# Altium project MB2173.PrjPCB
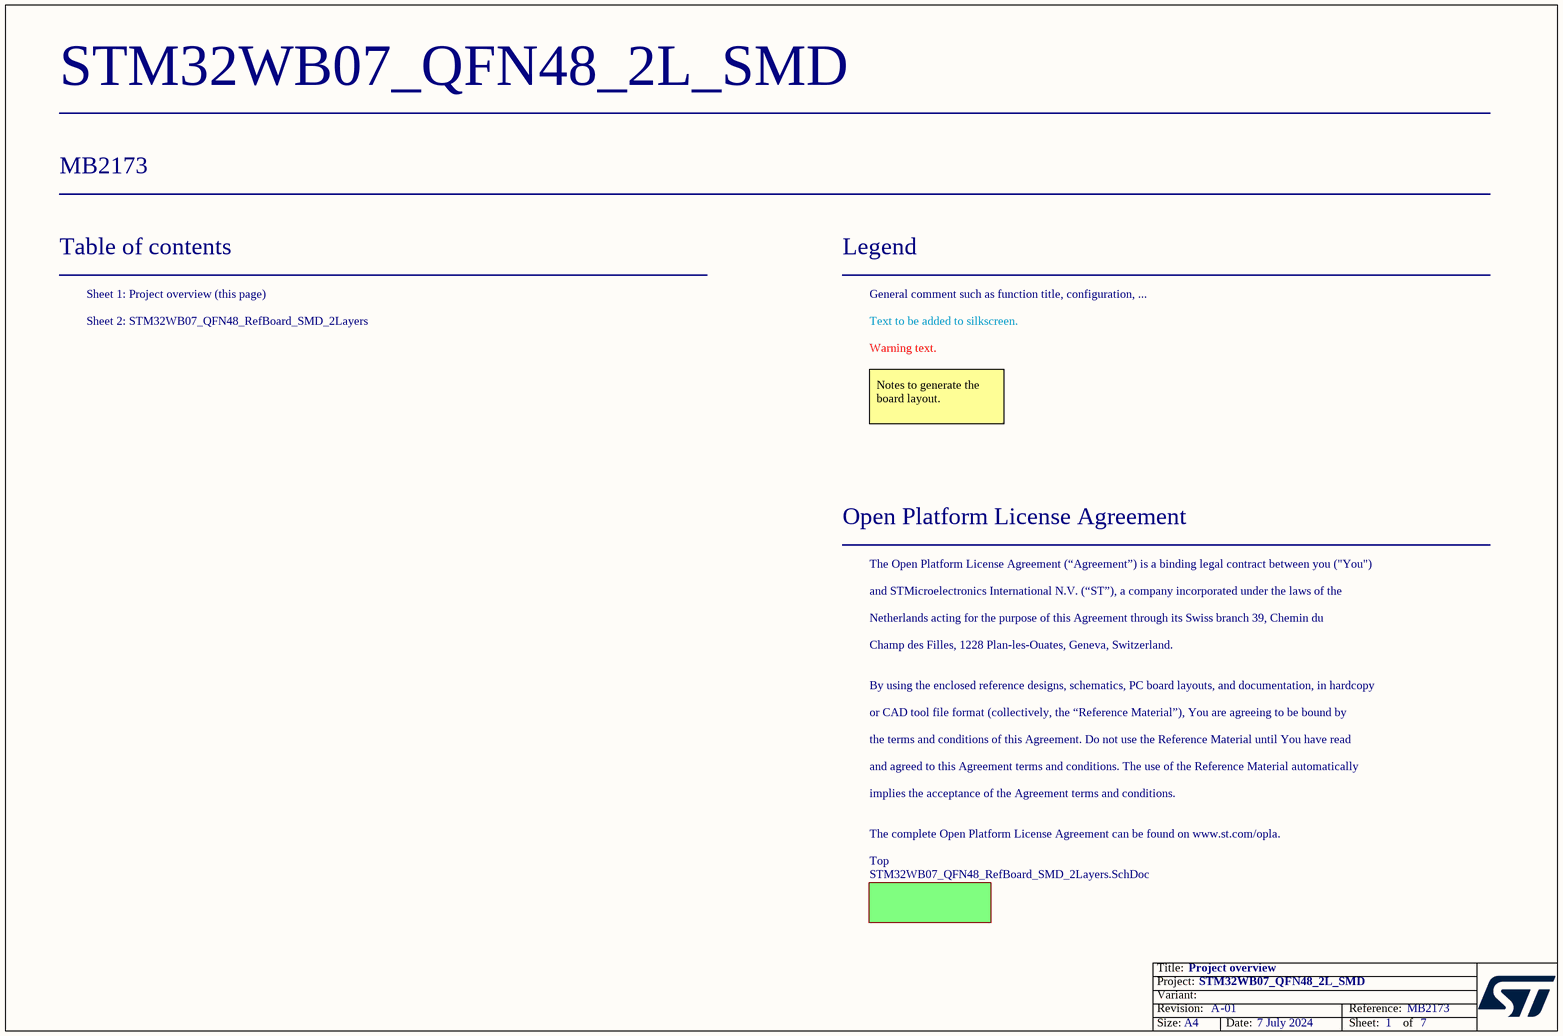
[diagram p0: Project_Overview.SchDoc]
Board_Reference: MB2173; Board_PCB_Revision: A; Board_Name: STM32WB07_QFN48_2L_SMD; Board_Document_Date: 7 July 2024; Board_Assembly_Revision: 01
2 sheets, 40 parts. Net scope: global (net labels, ports and power ports of the same name join across sheets).
Board file: MB2173.PcbDoc
Sheets:
  Project_Overview.SchDoc
    Top = STM32WB07_QFN48_RefBoard_SMD_2Layers.SchDoc

## Sheet Project_Overview.SchDoc: Project overview
size A4; Date: Not used; ApprovedBy: Not used; CheckedBy: Not used; Author: Not used; CompanyName: STMicroelectronics; DrawnBy: Not used; Engineer: Not used; Organization: Not used; Address1: Not used; Address2: Not used; Address3: Not used; Address4: Not used; DocumentNumber: Not used; Revision: Not used; SheetNumber: 1; SheetTotal: 7

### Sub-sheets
Top = STM32WB07_QFN48_RefBoard_SMD_2Layers.SchDoc: no entries

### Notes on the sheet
- Table of contents
- Sheet 1: Project overview (this page)
- Legend
- General comment such as function title, configuration, ...
- Sheet 2: STM32WB07_QFN48_RefBoard_SMD_2Layers
- Text to be added to silkscreen.
- Warning text.
- Notes to generate the board layout.
- Open Platform License Agreement
- The Open Platform License Agreement (“Agreement”) is a binding legal contract between you ("You")
- and STMicroelectronics International N.V. (“ST”), a company incorporated under the laws of the
- Netherlands acting for the purpose of this Agreement through its Swiss branch 39, Chemin du
- Champ des Filles, 1228 Plan-les-Ouates, Geneva, Switzerland.
- By using the enclosed reference designs, schematics, PC board layouts, and documentation, in hardcopy
- or CAD tool file format (collectively, the “Reference Material”), You are agreeing to be bound by
- the terms and conditions of this Agreement. Do not use the Reference Material until You have read
- and agreed to this Agreement terms and conditions. The use of the Reference Material automatically
- implies the acceptance of the Agreement terms and conditions.
- The complete Open Platform License Agreement can be found on www.st.com/opla.

## Sheet STM32WB07_QFN48_RefBoard_SMD_2Layers.SchDoc: STM32WB07 QFN48 SMPS
size A3; Date: Not used; ApprovedBy: Not used; CheckedBy: Not used; Author: Not used; CompanyName: STMicroelectronics; DrawnBy: Not used; Engineer: Not used; Organization: Not used; Address1: Not used; Address2: Not used; Address3: Not used; Address4: Not used; DocumentNumber: Not used; Revision: Not used; SheetNumber: 2; SheetTotal: 2
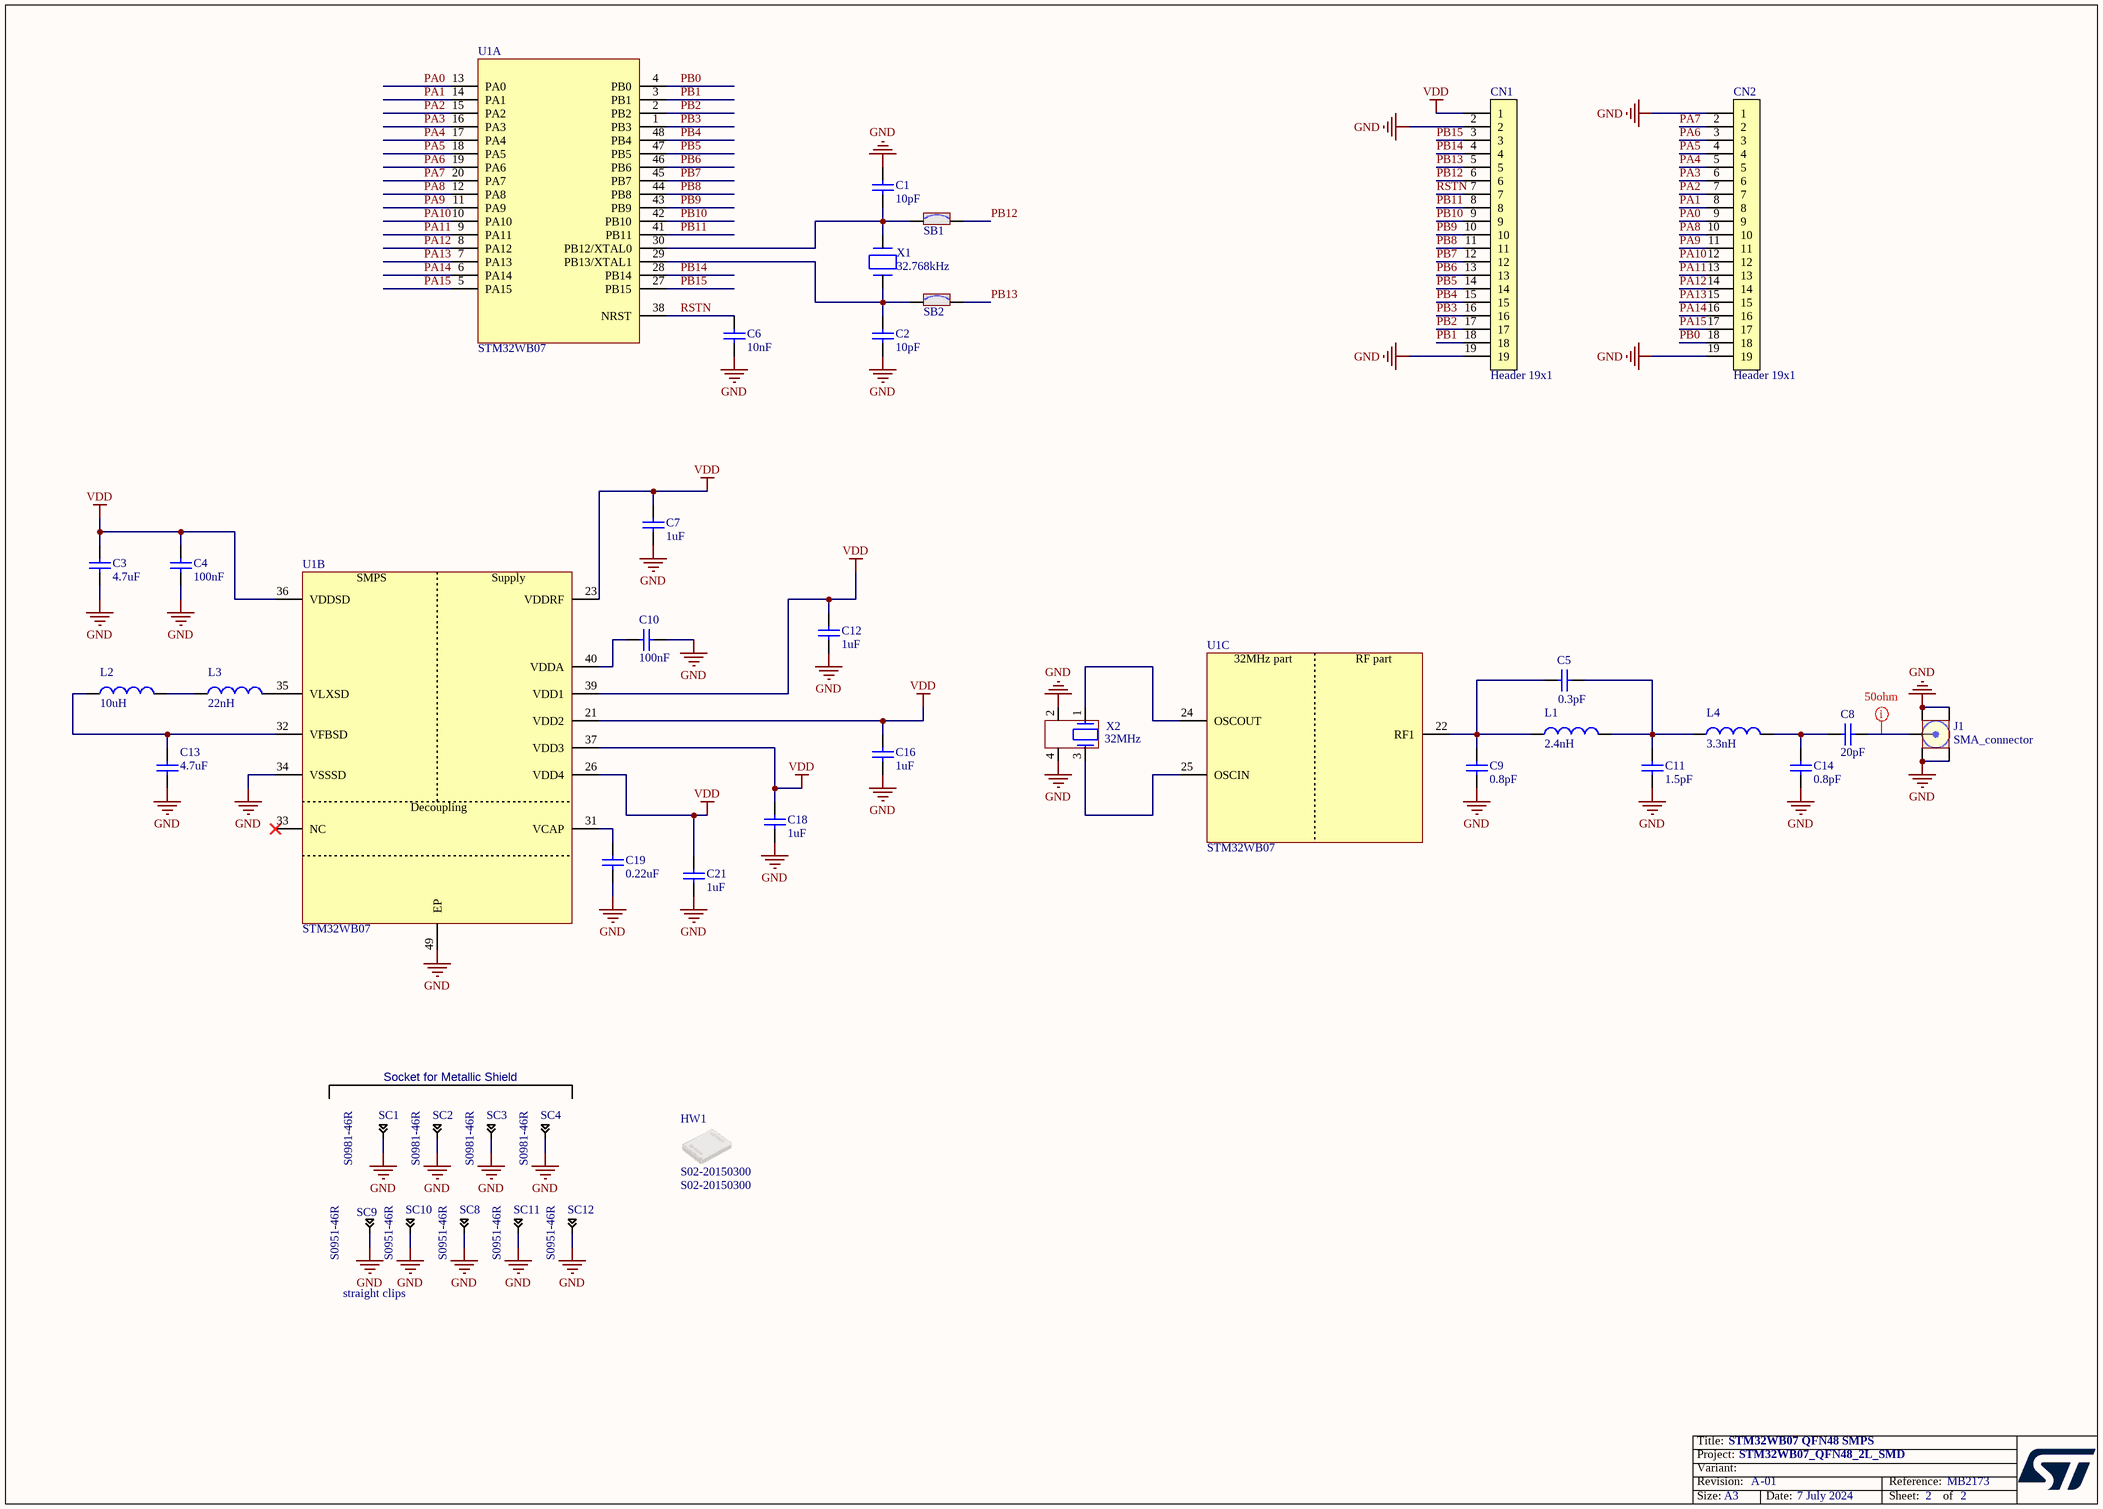
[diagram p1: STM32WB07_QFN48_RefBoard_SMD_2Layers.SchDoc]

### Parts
C1  value 10pF  [C0402]  (hidden comment: Capacitor)
C2  value 10pF  [C0402]  (hidden comment: Capacitor)
C3  value 4.7uF  [C0402]  (hidden comment: Capacitor)
C4  value 100nF  [C0201_H0P3]  (hidden comment: Capacitor)
C5  value 0.3pF  [0_5p_capacitor_SMD_0201]  (hidden comment: Capacitor)
C6  value 10nF  [C0402]  (hidden comment: Capacitor)
C7  value 1uF  [C0402]  (hidden comment: Capacitor)
C8  value 20pF  [20p_capacitor_SMD_0201]  (hidden comment: Capacitor)
C9  value 0.8pF  [0_8p_capacitor_SMD_0201]  (hidden comment: Capacitor)
C10  value 100nF  [C0402]  (hidden comment: Capacitor)
C11  value 1.5pF  [1_5p_capacitor_SMD_0201]  (hidden comment: Capacitor)
C12  value 1uF  [C0402]  (hidden comment: Capacitor)
C13  value 4.7uF  [C0402]  (hidden comment: Capacitor)
C14  value 0.8pF  [0_8p_capacitor_SMD_0201]  (hidden comment: Capacitor)
C16  value 1uF  [C0402]  (hidden comment: Capacitor)
C18  value 1uF  [C0402]  (hidden comment: Capacitor)
C19  value 0.22uF  [C0402]  (hidden comment: Capacitor)
C21  value 1uF  [C0402]  (hidden comment: Capacitor)
CN1  Header 19x1  [header_19x1]
CN2  Header 19x1  [header_19x1]
HW1  S02-20150300  [SHIELD_HARWIN_S02-20150300_15X20_H3]
J1  SMA_connector  [SMA_AMPHENOL_132415]
L1  value 2.4nH  [2n4_inductor_SMD_0201]  (hidden comment: Inductor)
L2  value 10uH  [IND_0805_MURATA_LQM21]  (hidden comment: Inductor)
L3  value 22nH  [C0402]  (hidden comment: Inductor)
L4  value 3.3nH  [3n3_inductor_SMD_0201]  (hidden comment: Inductor)
SB1  SB_ON  [SOLDER-BRIDGE_R0402-0R]  (value not drawn)
SB2  SB_ON  [SOLDER-BRIDGE_R0402-0R]  (value not drawn)
SC1  value S0981-46R  [CLIP_HARWIN_S0981-46R]  (hidden comment: Shield-clip_S0951-46R)
SC2  value S0981-46R  [CLIP_HARWIN_S0981-46R]  (hidden comment: Shield-clip_S0951-46R)
SC3  value S0981-46R  [CLIP_HARWIN_S0981-46R]  (hidden comment: Shield-clip_S0951-46R)
SC4  value S0981-46R  [CLIP_HARWIN_S0981-46R]  (hidden comment: Shield-clip_S0951-46R)
SC8  value S0951-46R  [CLIP_HARWIN_S0951-46R]  (hidden comment: Shield-clip_S0951-46R)
SC9  value S0951-46R  [CLIP_HARWIN_S0951-46R]  (hidden comment: Shield-clip_S0951-46R)
SC10  value S0951-46R  [CLIP_HARWIN_S0951-46R]  (hidden comment: Shield-clip_S0951-46R)
SC11  value S0951-46R  [CLIP_HARWIN_S0951-46R]  (hidden comment: Shield-clip_S0951-46R)
SC12  value S0951-46R  [CLIP_HARWIN_S0951-46R]  (hidden comment: Shield-clip_S0951-46R)
U1  STM32WB07  [ICC_QFN48-EPAD-4P5X4P5_6X6_P040]  (parts A,B,C of 3)
X1  value 32.768kHz  [CRY_NX2012SA_2P]  (hidden comment: XTAL_2_PINS)
X2  value 32MHz  [CRY_NX2016SA_4P]  (hidden comment: XTAL_4_PINS)

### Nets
GND: C1.2 C2.1 C3.1 C4.1 C6.2 C7.1 C9.1 C10.2 C11.1 C12.1 C13.1 C14.1 C16.1 C18.1 C19.1 C21.1 CN1.2 CN1.19 CN2.1 CN2.19 J1.2(Y) SC1.1 SC2.1 SC3.1 SC4.1 SC8.1 SC9.1 SC10.1 SC11.1 SC12.1 U1.34(VSSSD) U1.49(EP) X2.2 X2.4
VDD: C3.2 C4.2 C7.2 C12.2 C16.2 C18.2 C21.2 CN1.1 U1.21(VDD2) U1.23(VDDRF) U1.26(VDD4) U1.36(VDDSD) U1.37(VDD3) U1.39(VDD1)
PA0: CN2.9 U1.13(PA0)
PA1: CN2.8 U1.14(PA1)
PA2: CN2.7 U1.15(PA2)
PA3: CN2.6 U1.16(PA3)
PA4: CN2.5 U1.17(PA4)
PA5: CN2.4 U1.18(PA5)
PA6: CN2.3 U1.19(PA6)
PA7: CN2.2 U1.20(PA7)
PA8: CN2.10 U1.12(PA8)
PA9: CN2.11 U1.11(PA9)
PA10: CN2.12 U1.10(PA10)
PA11: CN2.13 U1.9(PA11)
PA12: CN2.14 U1.8(PA12)
PA13: CN2.15 U1.7(PA13)
PA14: CN2.16 U1.6(PA14)
PA15: CN2.17 U1.5(PA15)
PB0: CN2.18 U1.4(PB0)
PB1: CN1.18 U1.3(PB1)
PB2: CN1.17 U1.2(PB2)
PB3: CN1.16 U1.1(PB3)
PB4: CN1.15 U1.48(PB4)
PB5: CN1.14 U1.47(PB5)
PB6: CN1.13 U1.46(PB6)
PB7: CN1.12 U1.45(PB7)
PB8: CN1.11 U1.44(PB8)
PB9: CN1.10 U1.43(PB9)
PB10: CN1.9 U1.42(PB10)
PB11: CN1.8 U1.41(PB11)
PB12: CN1.6 SB1.1
PB13: CN1.5 SB2.1
PB14: CN1.4 U1.28(PB14)
PB15: CN1.3 U1.27(PB15)
RSTN: C6.1 CN1.7 U1.38(NRST)
NetC1_1: C1.1 SB1.2 U1.30(PB12/XTAL0) X1.1(X1)
NetC2_2: C2.2 SB2.2 U1.29(PB13/XTAL1) X1.2(X2)
NetC5_1: C5.1 C9.2 L1.1 U1.22(RF1)
NetC5_2: C5.2 C11.2 L1.2 L4.1
NetC8_1: C8.1 C14.2 L4.2
NetC8_2: C8.2 J1.1(X)
NetC10_1: C10.1 U1.40(VDDA)
NetC13_2: C13.2 L2.1 U1.32(VFBSD)
NetC19_2: C19.2 U1.31(VCAP)
NetL2_2: L2.2 L3.1
NetL3_2: L3.2 U1.35(VLXSD)
NetU1_24: U1.24(OSCOUT) X2.1
NetU1_25: U1.25(OSCIN) X2.3

Not connected (* = marked no-connect by the designer): U1 33(NC)*

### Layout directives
net class 50ohm: NetC8_2

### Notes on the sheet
- Socket for Metallic Shield
- straight clips

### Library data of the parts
C1 C2 = MCD-00015: Capacitor, MLCC, 10pF, 50V, NPO, +/-5%, 0402, T=0.5mm; Part_Preference: Recommended; Manufacturer: YAGEO; Manufacturer_Part_Number: CC0402JRNPO9BN100; Order_Code_RS: 3019160RL; Component_Country_Of_Origin: China; ShowFields: YES; ID: 2465
C3 C13 = MCD-03431: Capacitor, MLCC, 4.7uF, X5R, 10V, +/-20%, 0402, T=0.5mm; Part_Preference: Recommended; Manufacturer: MURATA; Manufacturer_Part_Number: GRM155R61A475MEAAD; Order_Code_RS: 172-6870; ShowFields: YES; ID: 5547; Component_Country_Of_Origin: China, Japan, Philippines, Singapore
C4 = MCD-01535: Capacitor, MLCC,100nF, 10V, X5R, +/-10%, 0201, T=0.3mm; Part_Preference: Recommended; Manufacturer: MURATA; Manufacturer_Part_Number: GRM033R61A104KE15; Order_Code_RS: 790-2742; Component_Country_Of_Origin: Japan; ShowFields: YES; ID: 3635
C5 = MCD-02284_4: 0201 0.3 pF 25 V ±0.05 pF Tolerance C0G SMT Multilayer Ceramic Capacitor; Manufacturer: Murata; Manufacturer Part Number: GJM0335C1ER30WB01D
C6 = MCD-00011: Capacitor, MLCC, 10nF, 16V, X7R, +/-10%, 0402, T=0.5mm; Part_Preference: Recommended; Manufacturer: YAGEO; Manufacturer_Part_Number: CC0402KRX7R7BB103; Order_Code_RS: 3019275; Component_Country_Of_Origin: China; ShowFields: YES; ID: 2469
C7 C12 C16 C18 C21 = MCD-03432: Capacitor, MLCC, 1uF, X7R, 6.3V,+/- 10%, 0402, T=0.5mm; Part_Preference: Recommended; Manufacturer: MURATA; Manufacturer_Part_Number: GRM155R70J105KA12; Order_Code_RS: 113-8711; ShowFields: YES; ID: 5548; Component_Country_Of_Origin: China, Japan, Philippines, Singapore
C8 = MCD-03543: Capacitor, MLCC, 20pF, 25V, COG, +/-2%, 0201, T=0.3mm; Part_Preference: Recommended; Manufacturer: MURATA; Manufacturer_Part_Number: GJM0335C1E200GB01; ShowFields: YES; ID: 5659; Component_Country_Of_Origin: Japan, Singapore
C9 C14 = MCD-02284_1: Multilayer Ceramic Capacitor, 0.8 pF, 25 V, ± 0.05pF, C0G (NP0), 0201 [0603 Metric]; Manufacturer: Murata; Manufacturer Part Number: GJM0335C1ER80WB01D; Material: 4241ConductorMaterial; Temperature Coefficient: 30ppm/°C
C10 = MCD-02355: Capacitor, MLCC, 100nF, 25V, X7R, +/-10%, 0402, T=0.5mm; Part_Preference: Recommended; Manufacturer: WALSIN; Manufacturer_Part_Number: 0402B104K250CT; Partial_Alternate_Internal_Part_Number: MCD-03302, MCD-03304; Order_Code_RS: 176-3114; Component_Country_Of_Origin: Unknown; ShowFields: YES; ID: 4461
C11 = MCD-02284_3: Multilayer Ceramic Capacitor, 1.5 pF, 25 V, ± 0.1pF, C0G (NP0), 0201 [0603 Metric]; Manufacturer: Murata; Manufacturer Part Number: GJM0335C1E1R5BB01D; Voltage Rating: 25V
C19 = MCD-03483: Capacitor, MLCC, 0.22uF, X5R, 6.3V, +/-10%, 0402, T=0.5mm; Part_Preference: Recommended; Manufacturer: YAGEO; Manufacturer_Part_Number: CC0402KRX5R5BB224; Order_Code_RS: 3369131; ShowFields: YES; ID: 5599; Component_Country_Of_Origin: China
CN1 CN2 = HEADER_19X1: Header, 18x1, 2.54mm, VR, TH, T=5.84mm/8.38mm; Internal_Part_Number: MCD-01897; Part_Type: Connector; Part_Preference: Recommended; Manufacturer: SAMTEC; Manufacturer_Part_Number: TSW-118-07-L-S; Order_Code_RS: 767-1141; Component_Country_Of_Origin: China, Costa Rica, Malaysia, United States, Vietnam; ShowFields: YES; ID: 3997
HW1 = MCD-03126: RFI shield can, 20x15x3mm; Part_Type: Misc; Part_Preference: Recommended; Manufacturer: HARWIN; Order_Code_RS: 161-3687; Component_Country_Of_Origin: UK°; ShowFields: YES; ID: 5242
J1 = SMA_connector: Rf Connector, Sma End Launch Recept Jack For .032" Pcb / Individual Bag; Manufacturer: Amphenol Connex; Manufacturer Part Number: 132415; Note: Replacement with compatible component is forbidden.
L1 = MCD-03552: Inductor RF Chip Thin Film 2.4nH 0.1nH 500MHz 14Q-Factor 500mA 200mOhm DCR 0201 Paper T/R; Manufacturer: Murata; Manufacturer Part Number: LQP03TN2N4B02D
L2 = MCD-03438: Inductor, MLCC, 10uH, +/-20%, 300mA, 845mR, 0805, T=1.45mm; Part_Preference: Recommended; Manufacturer: MURATA; Manufacturer_Part_Number: LQM21DN100M70L; Order_Code_RS: NA; ShowFields: YES; ID: 5554; Component_Country_Of_Origin: Japan
L3 = MCD-03439: Inductor, MLCC, 22nH, +/-2%, 350mA, 0.58R, 0402, T=1.45mm; Part_Preference: Recommended; Manufacturer: MURATA; Manufacturer_Part_Number: LQG15HN22NG02D; Order_Code_RS: 3354168; ShowFields: YES; ID: 5555; Component_Country_Of_Origin: Japan
L4 = MCD-03552_1: Inductor RF Chip Thin Film 3.3nH 0.1nH 500MHz 14Q-Factor 450mA 250mOhm DCR 0201 Paper T/R; Manufacturer: Murata; Manufacturer Part Number: LQP03TN3N3B02D
SB1 SB2 = MCD-01618: Resistor, 0R, SB0402, 5%, 0.063W; Part_Preference: Recommended; Manufacturer: YAGEO; Manufacturer_Part_Number: RC0402JR-070RL; Order_Code_RS: 618-5804; Component_Country_Of_Origin: China; ShowFields: YES; ID: 3718
SC1-SC4 = MCD-02164: Shield clip Harwin S0981-46R to fix RF shielded cavity; Part_Type: Mechanical; Part_Preference: Recommended; Order_Code_RS: 161-3702; Component_Country_Of_Origin: South Korea; ShowFields: YES; ID: 4264
SC8-SC12 = MCD-01587: RFI shield clip mini TIN SMD; Part_Type: Mechanical; Part_Preference: Recommended; Manufacturer: HARWIN; Component_Country_Of_Origin: South Korea; ShowFields: YES; ID: 3687
U1 = MCD-03836: IC, Bluetooth Low Energy wireless SoC, QFN48; Part_Preference: Recommended; Manufacturer: STMICROELECTRONICS; Manufacturer_Part_Number: STM32WB07CCV6UTR; Full_Alternate_Internal_Part_Number: NA; Component_Country_Of_Origin: Unknown; ShowFields: YES; ID: 5952
X1 = MCD-01445: Crystal, 32.768kHz, 7pF, +/-20ppm, 80K, 2.05x1.2mm; BMS_Part_Number: 9157043; Part_Type: Crystal_Osc; Part_Preference: Recommended; Manufacturer: NDK; Manufacturer_Part_Number: NX2012SA-32.768KHZ-EXS00A-MU00389; Component_Country_Of_Origin: Unknown; ShowFields: YES; ID: 3545
X2 = MCD-01446: Crystal, 32MHz, 8pF, +/-10ppm, 60R, 2x1.6mm; BMS_Part_Number: 9157042; Part_Type: Crystal_Osc; Part_Preference: Recommended; Manufacturer: NDK; Manufacturer_Part_Number: NX2016SA-32MHZ-EXS00A-CS06654; Component_Country_Of_Origin: Unknown; ShowFields: YES; ID: 3546

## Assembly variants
Variant A: not fitted CN1 CN2 SB1 SB2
